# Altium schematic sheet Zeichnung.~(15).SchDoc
size A4; PageSetup: Record=PageOptions¦CenterHorizontal=True¦CenterVertical=True¦PrintScale=1.00¦XCorrection=1.00¦YCorrection=1.00¦PrintKind=0¦BorderSize=5000000¦LeftOffset=0¦BottomOffset=0¦Orientation=2¦PaperLength=1000¦PaperWidth=1000¦Scale=100¦PaperSource=7¦PrintQuality=-3¦MediaType=1¦DitherType=10¦PrintScaleMode=1¦PaperKind=A4¦PaperIndex=9
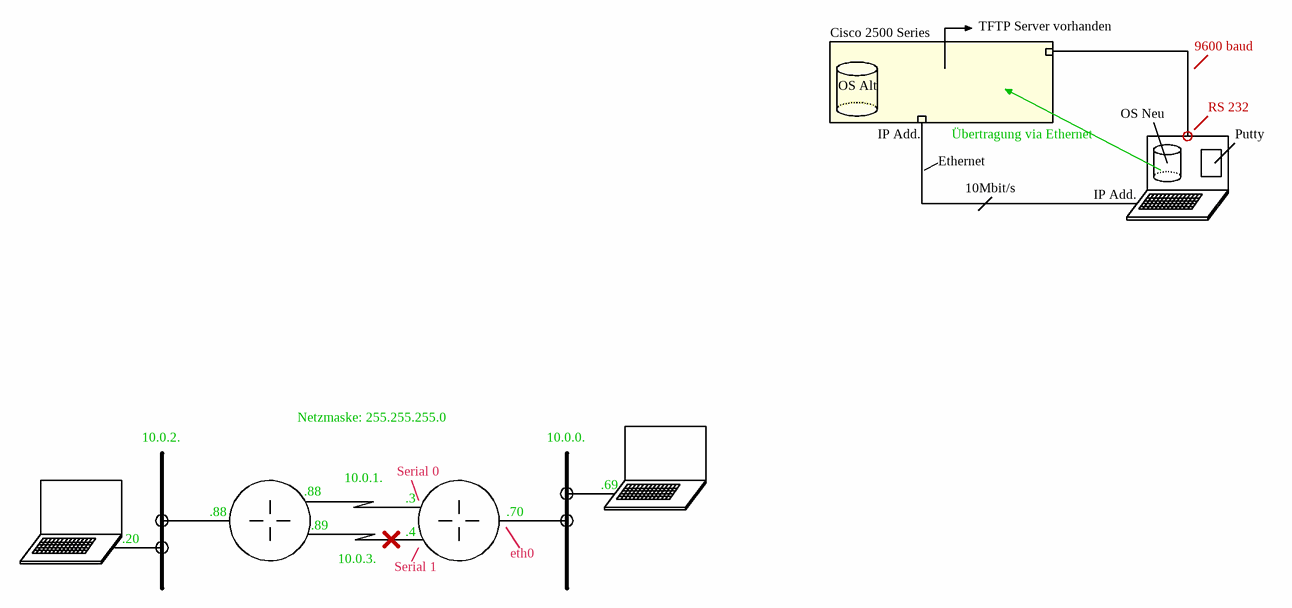
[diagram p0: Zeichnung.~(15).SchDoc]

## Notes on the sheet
- Cisco 2500 Series
- TFTP Server vorhanden
- 9600 baud
- OS Alt
- IP Add.
- Übertragung via Ethernet
- OS Neu
- RS 232
- Putty
- Ethernet
- 10Mbit/s
- 10.0.2.
- Netzmaske: 255.255.255.0
- 10.0.1.
- Serial 0
- 10.0.0.
- .20
- .88
- .89
- .3
- .4
- .70
- .69
- 10.0.3.
- Serial 1
- eth0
